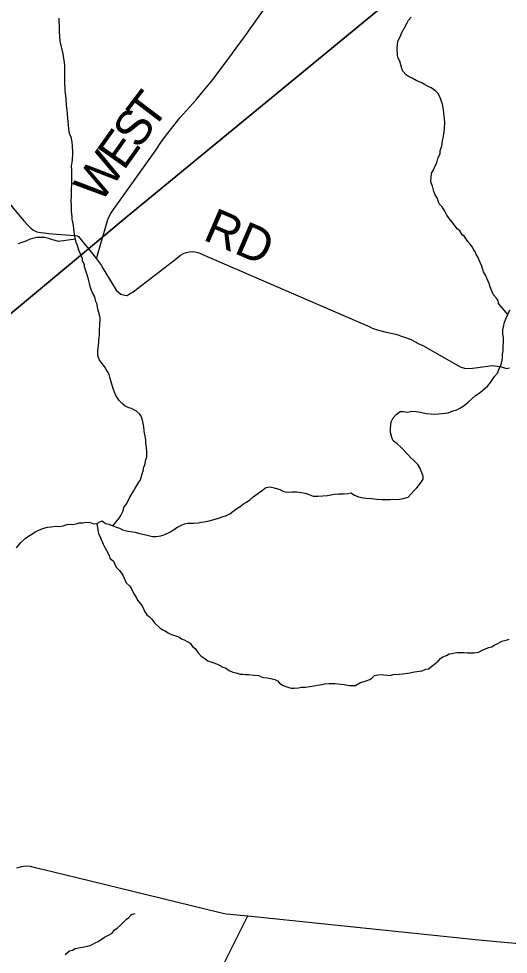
# Model space of a CAD drawing. Extents: x 1310247 to 1664935, y 235267 to 584339.
# Drawn here: x 1493259 to 1497464, y 331618 to 339657 of the extents above; entities that cross this region are included whole.
import ezdxf

# ---------------------------------------------------------------- set-up
doc = ezdxf.new("R2010")
doc.units = 0
for name, color, linetype in [('GM_X_County_Road', 7, 'Continuous'), ('GM_X_Minor_River', 7, 'Continuous'), ('GM_X_Township', 7, 'Continuous'), ('GM_X_Township_Road', 7, 'Continuous'), ('GM_X_Township_Road_Text', 7, 'Continuous')]:
    doc.layers.add(name, color=color, linetype=linetype)

msp = doc.modelspace()

# ---------------------------------------------------------------- linework, layer by layer
at = {"layer": 'GM_X_County_Road'}
msp.add_lwpolyline([(1493243.3, 332361), (1493285.6, 332372), (1493319.8, 332379.2), (1493357.7, 332376.2), (1493401.5, 332365.1), (1493475.1, 332347.2), (1493757.5, 332278), (1494988.6, 331976.5), (1495040.3, 331965.2), (1495226.7, 331948.4), (1497210.2, 331742.6), (1497863.3, 331681.1)], dxfattribs=at)
at = {"layer": 'GM_X_Minor_River'}
for points in [[(1493713.7, 338630.1), (1493696.4, 338670.6), (1493689, 338706.9), (1493685.7, 338745.1), (1493680.6, 338799.5), (1493677.3, 338839.7), (1493673.9, 338873.9), (1493670.6, 338912.1), (1493665.6, 338970.5), (1493664, 338990.6), (1493658.9, 339042.9), (1493657.3, 339065), (1493655.8, 339095.2), (1493656.5, 339129.4), (1493655.4, 339181.6), (1493656.2, 339227.8), (1493654.7, 339251.9), (1493653.2, 339282.1), (1493644.1, 339334.5), (1493640.4, 339354.6), (1493625.5, 339415.2), (1493614.3, 339465.6), (1493611, 339507.8), (1493609.7, 339544), (1493610.1, 339568.1), (1493608.7, 339598.3), (1493607.2, 339630.5), (1493605.8, 339660.6)], [(1497459.4, 337114.6), (1497380.2, 337209.1), (1497376.6, 337235.2), (1497359, 337257.6), (1497337.3, 337284.1), (1497318.1, 337330.7), (1497306.6, 337363), (1497298.9, 337383.3), (1497289.3, 337407.5), (1497268, 337454.1), (1497252.5, 337482.5), (1497237.3, 337531), (1497214.1, 337583.6), (1497206.5, 337605.9), (1497188.8, 337630.3), (1497181.1, 337650.5), (1497169.5, 337670.8), (1497153.8, 337697.2), (1497140.1, 337717.5), (1497116.5, 337742.1), (1497089.1, 337784.7), (1497069.3, 337801.1), (1497047.8, 337833.7), (1497026, 337852.1), (1497010.3, 337872.5), (1496984.8, 337905.1), (1496969.1, 337927.4), (1496951.4, 337949.8), (1496935.7, 337970.2), (1496918.2, 338004.7), (1496894.8, 338041.2), (1496871.1, 338065.8), (1496853.9, 338118.3), (1496836.3, 338144.7), (1496824.8, 338173), (1496813.5, 338217.4), (1496802, 338245.8), (1496798.3, 338265.9), (1496800.7, 338286), (1496805.5, 338330.1), (1496818, 338354), (1496838.9, 338399.8), (1496849.4, 338419.8), (1496862.2, 338463.7), (1496878.9, 338497.6), (1496879.3, 338521.7), (1496892.2, 338563.7), (1496899, 338607.8), (1496903.4, 338629.8), (1496912.4, 338683.9), (1496917, 338716), (1496917.9, 338766.2), (1496916.5, 338796.3), (1496913, 338826.5), (1496911.4, 338848.7), (1496907.8, 338874.9), (1496898.7, 338923.2), (1496891, 338945.5), (1496881.4, 338971.7), (1496862.1, 339014.3), (1496840.4, 339034.7), (1496802.7, 339063.5), (1496782.8, 339071.9), (1496744.9, 339092.6), (1496721.1, 339105.1), (1496673.2, 339126), (1496643.4, 339144.6), (1496613.5, 339159.2), (1496587.6, 339173.7), (1496558.1, 339206.3), (1496548.4, 339228.6), (1496531.5, 339293.2), (1496516, 339323.6), (1496512.4, 339345.7), (1496509.3, 339398), (1496512, 339438.1), (1496516.5, 339462.2), (1496524.9, 339482.1), (1496537.4, 339508), (1496545.9, 339532), (1496572.9, 339579.8), (1496595.7, 339621.5), (1496606.2, 339643.5), (1496628.8, 339671.2)], [(1494066.3, 335300), (1494121, 335365.8), (1494137.5, 335389.6), (1494156.3, 335429.5), (1494162.9, 335457.5), (1494185.5, 335487.3), (1494198.1, 335515.2), (1494212.7, 335547.1), (1494245.8, 335598.8), (1494256.2, 335618.7), (1494289.4, 335674.4), (1494303.8, 335694.2), (1494318.8, 335746.2), (1494329.5, 335780.2), (1494331.9, 335802.3), (1494342.3, 335822.2), (1494351.2, 335868.3), (1494359.6, 335890.2), (1494358.4, 335932.5), (1494355.2, 335976.7), (1494351.8, 336013), (1494350.1, 336033.1), (1494346.6, 336059.3), (1494339.2, 336095.6), (1494335.6, 336119.7), (1494334.2, 336149.9), (1494324.9, 336194.3), (1494319.3, 336218.5), (1494311.7, 336242.7), (1494296, 336263.1), (1494270.3, 336285.6), (1494246.4, 336296.1), (1494226.5, 336306.5), (1494204.5, 336312.9), (1494174.6, 336327.5), (1494150.8, 336348), (1494123.2, 336376.6), (1494093.8, 336419.3), (1494080.3, 336447.7), (1494072.6, 336469.9), (1494065.1, 336498.2), (1494051.7, 336536.6), (1494044.2, 336564.8), (1494034.8, 336599.1), (1494021.2, 336625.5), (1494007.5, 336647.8), (1493995.9, 336670.1), (1493952.6, 336723.1), (1493943, 336745.4), (1493937.3, 336767.6), (1493937.9, 336797.8), (1493942.5, 336829.8), (1493947.3, 336874), (1493947.7, 336894), (1493952.5, 336940.2), (1493953.5, 336992.4), (1493955.9, 337016.5), (1493957.2, 337086.8), (1493953.6, 337113), (1493942.3, 337153.3), (1493934.7, 337179.6), (1493933.2, 337203.8), (1493921.5, 337226), (1493912.2, 337266.4), (1493892.7, 337302.9), (1493885.1, 337323.1), (1493873.6, 337357.5), (1493858.7, 337420), (1493841.5, 337472.6), (1493834, 337500.8), (1493824.4, 337525.1), (1493822.8, 337545.2), (1493807.3, 337577.6), (1493807.6, 337597.7), (1493786.3, 337642.3), (1493776.8, 337668.6), (1493763.4, 337709), (1493751.8, 337733.3), (1493746.3, 337763.5), (1493740.7, 337785.8), (1493735.5, 337830), (1493731.8, 337850.2), (1493728.4, 337882.4), (1493717.2, 337934.8), (1493717.7, 337958.9), (1493712.4, 338001.2), (1493711, 338033.4), (1493711.5, 338063.5), (1493709.9, 338083.7), (1493712.8, 338135.8), (1493715.7, 338294.5), (1493714.4, 338332.7), (1493714.8, 338352.8), (1493713.5, 338395), (1493718, 338419.1), (1493723.2, 338485.3), (1493723.7, 338511.4), (1493720.6, 338563.7), (1493717.1, 338593.9), (1493713.7, 338630.1)], [(1493746.3, 337763.5), (1493601.2, 337743.9), (1493573.3, 337752.5), (1493549.2, 337756.9), (1493515.3, 337769.5), (1493481.2, 337776.1), (1493453.1, 337778.6), (1493414.9, 337777.3), (1493358.4, 337762.2), (1493319.9, 337746.8), (1493285.5, 337733.3), (1493255.2, 337721.7)], [(1496672.8, 336283.2), (1496706.7, 336276.6), (1496732.7, 336270.1), (1496762.6, 336263.6), (1496794.6, 336263), (1496832.5, 336258.4), (1496868.6, 336261.8), (1496920.8, 336266.9), (1496946.8, 336270.5), (1496989.2, 336287.8), (1497023.3, 336295.3), (1497053.7, 336314.8), (1497084, 336332.4), (1497120.5, 336361.9), (1497147, 336387.5), (1497183.5, 336419), (1497213.9, 336440.5), (1497242.3, 336462.1), (1497287, 336503.5), (1497311.5, 336531.2), (1497344.4, 336582.8), (1497370.9, 336612.5), (1497385.5, 336648.3), (1497404.2, 336686.1), (1497412.8, 336722.1), (1497413.2, 336748.2), (1497415.7, 336776.2), (1497420.1, 336802.2), (1497422, 336916.6), (1497416.6, 336950.8), (1497417.1, 336982.9), (1497421.6, 337010.9), (1497430.2, 337048.8), (1497446.9, 337084.7), (1497459.4, 337114.6), (1497478.1, 337154.4)], [(1493976.9, 335343.6), (1494004.6, 335319.1), (1494032.5, 335312.6), (1494066.3, 335300), (1494098.1, 335289.4), (1494126, 335278.9), (1494151.8, 335266.4), (1494185.6, 335255.8), (1494219.6, 335251.2), (1494259.5, 335244.5), (1494287.4, 335238), (1494325.3, 335229.4), (1494363.2, 335218.7), (1494407, 335207.9), (1494441, 335207.3), (1494479.2, 335212.7), (1494515.4, 335226.1), (1494555.8, 335245.5), (1494590.2, 335269), (1494622.5, 335288.5), (1494656.9, 335306), (1494683.1, 335317.6), (1494709.2, 335321.2), (1494763.2, 335322.3), (1494801.3, 335325.6), (1494829.4, 335331.2), (1494883.6, 335340.3), (1494925.8, 335351.6), (1494974.1, 335364.8), (1495014.4, 335380.2), (1495044.6, 335389.7), (1495072.8, 335403.3), (1495099.2, 335422.9), (1495133.6, 335448.4), (1495159.9, 335466), (1495190.3, 335487.6), (1495216.6, 335503.2), (1495245, 335522.8), (1495271.4, 335548.4), (1495352.4, 335605.2), (1495380.8, 335628.8), (1495419, 335636.2), (1495452.9, 335627.6), (1495500.6, 335610.8), (1495526.5, 335598.3), (1495562.3, 335589.6), (1495604.4, 335593), (1495646.5, 335592.2), (1495688.4, 335585.5), (1495720.3, 335581), (1495746.2, 335572.5), (1495787.9, 335553.7), (1495828, 335555.1), (1495872.1, 335558.3), (1495910.2, 335561.7), (1495940.3, 335567.2), (1495968.4, 335572.8), (1496006.4, 335574.1), (1496048.5, 335575.4), (1496084.6, 335578.8), (1496110.7, 335584.4), (1496142.4, 335563.8), (1496176.2, 335549.2), (1496218, 335540.4), (1496244, 335536), (1496288, 335533.2), (1496335.9, 335528.4), (1496373.9, 335525.8), (1496407.9, 335525.2), (1496450, 335526.5), (1496478, 335528), (1496514, 335525.4), (1496562.2, 335534.6), (1496604.5, 335545.9), (1496628.9, 335573.6), (1496653.4, 335601.3), (1496677.9, 335627), (1496710.6, 335666.5), (1496733.1, 335700.3), (1496733.6, 335726.3), (1496716.3, 335768.8), (1496704.8, 335799.1), (1496687.2, 335825.4), (1496651.7, 335860.1), (1496626.1, 335884.7), (1496602.6, 335913.1), (1496541.6, 335976.4), (1496510, 336003), (1496476.4, 336029.6), (1496464.9, 336060), (1496453.6, 336100.3), (1496452.2, 336138.4), (1496454.7, 336166.5), (1496459.1, 336192.5), (1496475.8, 336228.3), (1496500.2, 336256), (1496534.7, 336281.5), (1496562.7, 336283), (1496598.7, 336276.4), (1496636.8, 336283.8), (1496672.8, 336283.2)], [(1493342.2, 335211.9), (1493370.5, 335229.5), (1493400.9, 335247), (1493437.2, 335266.5), (1493473.5, 335279.9), (1493505.6, 335287.4), (1493537.7, 335290.9), (1493573.8, 335296.3), (1493609.8, 335293.7), (1493642, 335301.1), (1493684.2, 335314.5), (1493718.2, 335311.9), (1493752.3, 335317.3), (1493778.5, 335324.9), (1493810.5, 335326.4), (1493836.6, 335330), (1493872.6, 335327.3), (1493900.4, 335316.8), (1493930.5, 335320.3), (1493962.8, 335337.8), (1493976.9, 335343.6)], [(1493930.5, 335320.3), (1493945.7, 335230.1), (1493959.3, 335203.8), (1493984.3, 335143), (1493997.9, 335114.7), (1494009.6, 335094.4), (1494034.8, 335045.7), (1494042.4, 335021.5), (1494072.1, 334996.8), (1494083.7, 334970.5), (1494097.3, 334944.2), (1494128.9, 334913.5), (1494152.3, 334874.9), (1494181.3, 334810.1), (1494213, 334781.4), (1494230.5, 334753), (1494246, 334720.5), (1494269.4, 334679.9), (1494279.1, 334659.7), (1494320.5, 334612.8), (1494343.7, 334562.1), (1494359.3, 334535.7), (1494379.1, 334521.3), (1494402.8, 334498.8), (1494422.4, 334468.3), (1494473.7, 334419.2), (1494495.6, 334406.8), (1494517.5, 334396.3), (1494537.4, 334383.9), (1494571.2, 334365.3), (1494613.2, 334352.5), (1494633.2, 334346.1), (1494657, 334327.6), (1494678.9, 334319.2), (1494730.7, 334292.2), (1494752.3, 334263.7), (1494774.1, 334245.2), (1494799.6, 334208.6), (1494825.2, 334180), (1494849, 334165.6), (1494884.8, 334140.8), (1494926.7, 334124), (1494966.6, 334111.3), (1495012.4, 334086.4), (1495036.4, 334080), (1495066.1, 334057.3), (1495098, 334042.7), (1495126.1, 334036.2), (1495162, 334025.5), (1495184.1, 334025.2), (1495206.2, 334022.8), (1495232.3, 334022.3), (1495280.5, 334017.5), (1495320.6, 334012.8), (1495342.5, 334002.3), (1495364.5, 333995.9), (1495392.6, 333993.5), (1495434.6, 333984.7), (1495458.7, 333980.3), (1495482.6, 333967.8), (1495500.3, 333947.4), (1495530.1, 333926.8), (1495552, 333918.4), (1495578, 333909.9), (1495598, 333905.5), (1495624.1, 333905.1), (1495662.4, 333906.4), (1495688.6, 333912), (1495722.8, 333913.4), (1495795.3, 333924.2), (1495823.6, 333929.8), (1495865.9, 333937.1), (1495886.1, 333940.8), (1495922.3, 333944.2), (1495952.5, 333945.7), (1495976.6, 333945.3), (1496026.7, 333938.4), (1496054.8, 333935.9), (1496100.9, 333929.1), (1496151.2, 333928.2), (1496195.8, 333953.6), (1496244.3, 333966.8), (1496274.7, 333980.3), (1496295, 333994.1), (1496315.5, 334013.8), (1496343.7, 334019.4), (1496373.9, 334020.9), (1496396, 334020.5), (1496424.1, 334016), (1496448.1, 334013.5), (1496476.4, 334021.1), (1496526.7, 334024.3), (1496556.9, 334027.8), (1496579.1, 334029.4), (1496617.4, 334036.8), (1496659.8, 334046.1), (1496700.1, 334051.4), (1496724.3, 334055.1), (1496756.7, 334068.6), (1496778.8, 334072.2), (1496819.6, 334101.7)], [(1493240.5, 335111.3), (1493277.3, 335156.8), (1493315.8, 335190.3), (1493342.2, 335211.9)], [(1496819.6, 334101.7), (1496860.4, 334137.1), (1496882.9, 334158.9), (1496903.2, 334172.6), (1496933.6, 334186.1), (1496956, 334199.8), (1496978.2, 334203.5), (1497004.4, 334207), (1497024.5, 334210.7), (1497044.6, 334210.4), (1497084.8, 334211.7), (1497114.9, 334209.1), (1497151.1, 334208.5), (1497171.2, 334208.2), (1497207.5, 334213.6), (1497246, 334233), (1497296.6, 334254.3), (1497322.9, 334259.8), (1497343.2, 334273.6), (1497369.6, 334285.2), (1497408.2, 334308.6), (1497446.5, 334318), (1497470.8, 334325.6)], [(1493659.4, 331617.4), (1493694.1, 331647), (1493720.3, 331652.5), (1493742.7, 331668.2), (1493787.1, 331675.5), (1493821.4, 331683), (1493847.6, 331686.5), (1493875.8, 331694.1), (1493914.4, 331715.5), (1493942.7, 331727.1), (1493995.7, 331766.4), (1494030.2, 331781.9), (1494060.6, 331799.5), (1494081.3, 331829.2), (1494105.6, 331842.9), (1494132.2, 331868.6), (1494162.9, 331896.2), (1494183.4, 331919.9), (1494205.8, 331933.6), (1494228.3, 331959.4), (1494258.6, 331968.9)]]:
    msp.add_lwpolyline(points, dxfattribs=at)
at = {"layer": 'GM_X_Township'}
for points in [[(1474902.6, 317724.2), (1475415.4, 321906.2), (1475424.8, 322383.7), (1477153.5, 323824.7), (1482366.2, 328165.1), (1483452.9, 329069.8), (1486515.6, 331606), (1487825, 332723.4), (1489150.3, 333806.3), (1492086.9, 336205.7), (1493858.3, 337680), (1493981.8, 337782.7), (1494191.9, 337957.6), (1499473.1, 342306)], [(1499473.1, 342306), (1494191.9, 337957.6), (1493981.8, 337782.7), (1493858.3, 337680), (1492086.9, 336205.7), (1489150.3, 333806.3), (1487825, 332723.4), (1486515.6, 331606), (1483452.9, 329069.8), (1482366.2, 328165.1), (1477153.5, 323824.7)]]:
    msp.add_lwpolyline(points, dxfattribs=at)
at = {"layer": 'GM_X_Township_Road'}
for points in [[(1494116.9, 338079.1), (1494430.2, 338520), (1494486.5, 338602.7), (1494540.4, 338673.5), (1494646.1, 338807.1), (1494780.3, 338958), (1494846.5, 339038.4), (1494916.8, 339122.8), (1495022.7, 339264.4), (1495197.2, 339500.4), (1495386.6, 339768.1)], [(1492564.2, 338412), (1493020.5, 338193.8), (1493060, 338174.7), (1493097.3, 338149.7), (1493132.7, 338124.7), (1493167.6, 338083.7), (1493225.7, 338012), (1493303.3, 337921.8), (1493336.3, 337882.8), (1493359.7, 337860.2), (1493379.2, 337842), (1493414.8, 337826.7), (1493447.1, 337821), (1493478.6, 337817), (1493518.5, 337811.9), (1493582.4, 337806.2), (1493744.2, 337794), (1493763, 337791.8), (1493771.9, 337785.3), (1493783.6, 337770.9), (1493829.1, 337715.7)], [(1493971.1, 337746.1), (1493981.8, 337782.8), (1494001.9, 337851.5), (1494024, 337931.1), (1494047.4, 337980.6), (1494114, 338075.1), (1494116.9, 338079.1)], [(1493926.9, 337594.8), (1493941.6, 337645.1), (1493971.1, 337746.1)], [(1493829.1, 337715.7), (1493829.7, 337715), (1493849.4, 337691), (1493858.3, 337680), (1493926.9, 337594.8), (1493954, 337560), (1493969.3, 337535.5), (1493978.8, 337517.2), (1494000, 337484.6), (1494095.7, 337323.7), (1494119.2, 337305), (1494136.8, 337290.5), (1494170.6, 337281.6), (1494190.5, 337279.1), (1494225.2, 337302.3), (1494241.4, 337309.9), (1494613.2, 337595.6), (1494613.5, 337595.8)], [(1494613.5, 337595.8), (1494617.5, 337598.8), (1494648.2, 337626.1), (1494678.7, 337643.4), (1494698.8, 337648.8), (1494727, 337654.1), (1494751.1, 337657.5), (1494773, 337652.9), (1494808.9, 337646), (1494830.5, 337633.4), (1496274.6, 337008.3), (1496296.3, 336997.7), (1496347.9, 336980.3), (1496403.6, 336966.8), (1496499.1, 336946.3), (1496629.9, 336900.8), (1496671.3, 336878.1)], [(1496671.3, 336878.1), (1496672.3, 336877.5), (1496691.1, 336867.1), (1496734.5, 336846), (1497051.9, 336667.3), (1497095.5, 336652.1), (1497155.6, 336654.5), (1497203.9, 336661.3), (1497324.4, 336678.2), (1497390.2, 336668.5), (1497421.9, 336659.6), (1497447.8, 336653), (1497473.9, 336656.3)], [(1494602.2, 330809), (1494640.5, 330820.1), (1494667.1, 330841.5), (1494711.1, 330918.6), (1495226.7, 331948.4)]]:
    msp.add_lwpolyline(points, dxfattribs=at)

# ---------------------------------------------------------------- texts
at = {"layer": 'GM_X_Township_Road_Text'}
for s, rotation, p in [('T', 52.75854, (1494407.4, 338690.7)), ('S', 54.34605, (1494290.7, 338528)), ('E', 54.6337, (1494161.1, 338345.3)), ('W', 54.63921, (1493959.9, 338061.9)), ('RD', 336.69273, (1494832.4, 337761.5))]:
    msp.add_text(s, height=300, rotation=rotation, dxfattribs=at).set_placement(p)

doc.saveas('drawing.dxf')
